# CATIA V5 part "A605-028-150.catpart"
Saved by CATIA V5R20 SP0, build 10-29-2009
Part number: A605-028-150
Source: Unknown
Property "A": "0.000"
Property "ARTICLENO": "A605-028-150"
Property "BOMINFO": "A605-028-150"
Property "CODE": "A605-028-150"
Property "D": "9.000"
Property "FORM": "B"
Property "L": "150.000"
Property "L1": "60.000"
Property "LINA": "A605-028-150"
Property "NB": "A605-028-150"
Property "NBSYN": "$CODE."
Property "NN": "A605"
Property "NT": "Wear Plates, self-lubricating"
Property "SCREW": "3*M8X16"
Property "SUPPLIER": "CF"
Property "W": "28.000"
Bounding box of the stored display mesh (mm): x -28 to 0, y 0 to 5, z -150 to 0
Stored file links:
  C:\Users\Utente\Desktop\3D files A605\A605-028-150.catpart
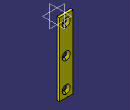
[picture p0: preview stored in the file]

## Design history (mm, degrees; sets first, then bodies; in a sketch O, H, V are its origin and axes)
Body1 "Geometry.1" (main body)
  Solid1 "A605-028-150.catpart": solid without history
